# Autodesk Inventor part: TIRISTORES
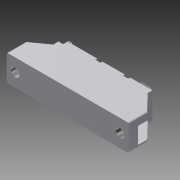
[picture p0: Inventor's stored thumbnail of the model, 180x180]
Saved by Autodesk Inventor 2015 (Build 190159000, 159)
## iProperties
Created: 2016-04
Part Number: TIRISTORES
Material: Genérico
Document SubType Name: Modeling
Designer: Diego
Density: 1 g/cm^3
Appearance: Blanco
Author: Diego
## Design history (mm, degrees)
sketch "Boceto1"
  geometry: L1 (0, 0)-(93, 0); L2 (93, 0)-(93, -20); L3 (93, -20)-(0, -20); L4 (0, -20)-(0, 0)
  constraints: 8 end point, 2 parallel, 1 horizontal, 1 perpendicular
  dimensions: "d0" = 93 distance of L2.end L3.end; "d1" = 20 distance of L1.end L2.end
extrude "Extrusión1" new body sketch "Boceto1" distance "d2" = 7; taper "d3" = 0 deg
sketch "Boceto2"
  geometry: L1 (-93, 0)-(0, 0) reference; 2 further points
hole "Agujero1" sketch "Boceto2" at (-86.5, 10), (-6.5, 10) diameter "d7" = 6.4; stored, may be unused: countersink angle "d11" = 90 deg, drill point angle "d13" = 118 deg; dims "d8" = 12, "d9" = 4, "d10" = 2, "d12" = 17.1
sketch "Boceto3"
  geometry: L1 (0, 0)-(-93, 0); L2 (-93, 0)-(-93, 2); L3 (-93, 2)-(0, 2); L4 (0, 2)-(0, 0)
  constraints: 8 end point, 2 parallel, 1 horizontal, 1 perpendicular
  dimensions: "d14" = 93 distance of L2.end L3.end; "d15" = 2 distance of L1.end L2.end
extrude "Extrusión2" join sketch "Boceto3" distance "d16" = 7; taper "d17" = 0 deg
sketch "Boceto4"
  geometry: L1 (0, 20)-(-93, 20); L2 (-93, 20)-(-93, 18); L3 (-93, 18)-(0, 18); L4 (0, 18)-(0, 20); 1 further point
  constraints: 8 end point, 2 parallel, 1 horizontal, 1 perpendicular
  dimensions: "d18" = 2 distance of L2.end L1.end
extrude "Extrusión3" join sketch "Boceto4" distance "d19" = 7; taper "d20" = 0 deg
sketch "Boceto5"
  geometry: L1 (-93, 20)-(0, 20) reference; L2 (0, 0)-(-93, 0) reference; L3 (-46.5, 20)-(-80.5, 20); L4 (-80.5, 20)-(-80.5, 0); L5 (-80.5, 0)-(-12.5, 0); L6 (-12.5, 0)-(-12.5, 20); L7 (-12.5, 20)-(-46.5, 20)
  constraints: 10 end point, 4 point on line, 1 collinear, 1 midpoint, 1 perpendicular
  dimensions: "d23" = 20 distance of L5.end L6.end
extrude "Extrusión4" join sketch "Boceto5" distance "d24" = 17; taper "d25" = 0 deg
sketch "Boceto6"
  geometry: L1 (0, 0)-(16, 0); L2 (16, 0)-(16, -7); L3 (16, -7)-(0, -7); L4 (0, -7)-(0, 0); 1 further point
  constraints: 8 end point, 2 parallel, 1 horizontal, 1 perpendicular
extrude "Extrusión5" join sketch "Boceto6" distance "d26" = 68; taper "d27" = 0 deg
sketch "Boceto7"
  geometry: L1 (12.5, 31)-(12.5, 27); L2 (12.5, 14)-(12.5, 31) reference; L3 (12.5, 27)-(0, 14); L4 (0, 14)-(12.5, 14); L5 (12.5, 14)-(0, 14) reference; L6 (12.5, 14)-(12.5, 27); 1 further point
  constraints: 8 end point, 1 collinear, 1 perpendicular, 1 point on line
  dimensions: "d28" = 4 distance of L1.start L1.end
extrude "Extrusión6" join sketch "Boceto7" distance "d29" = 2; taper "d30" = 0 deg
sketch "Boceto8"
  geometry: L1 (80.5, 31)-(80.5, 23); L2 (80.5, 14)-(80.5, 31) reference; L3 (80.5, 23)-(93, 14); L4 (93, 14)-(80.5, 14); L5 (80.5, 14)-(80.5, 23); 1 further point
  constraints: 8 end point, 1 collinear, 1 perpendicular, 1 point on line
  dimensions: "d31" = 8 distance of L1.start L1.end
extrude "Extrusión7" join sketch "Boceto8" distance "d32" = 2; taper "d33" = 0 deg
sketch "Boceto9"
  geometry: L1 (12.5, 23)-(0, 14); L2 (12.5, 23)-(0, 14) reference; L3 (0, 14)-(12.5, 14); L4 (12.5, 14)-(0, 14) reference; L5 (12.5, 14)-(12.5, 23); L6 (80.5, 27)-(93, 14); L7 (80.5, 27)-(93, 14) reference; L8 (93, 14)-(80.5, 14); L9 (93, 14)-(80.5, 14) reference; L10 (80.5, 14)-(80.5, 27); 1 further point
  constraints: 12 end point, 4 collinear, 2 perpendicular
extrude "Extrusión8" join sketch "Boceto9" distance "d34" = 2; taper "d35" = 0 deg
sketch "Boceto10"
  geometry: L1 (-80.5, 20)-(-74.5, 20); L2 (-93, 20)-(0, 20) reference; L3 (-74.5, 20)-(-74.5, 11); L4 (-74.5, 11)-(-80.5, 11); L5 (-80.5, 11)-(-80.5, 20); L6 (-74.5, 11)-(-74.5, 0); L7 (-74.5, 0)-(-80.5, 0); L8 (-80.5, 0)-(-12.5, 0) reference; L9 (-80.5, 0)-(-80.5, 9); L10 (-80.5, 20)-(-80.5, 0) reference; L11 (-80.5, 9)-(-74.5, 9); 1 further point
  constraints: 16 end point, 3 point on line, 2 perpendicular, 2 vertical, 1 collinear, 1 horizontal
  dimensions: "d36" = 6 distance of L1.start L1.end; "d37" = 9 distance of L1.end L3.end; "d38" = 9 distance of L7.end L9.end
extrude "Extrusión9" cut sketch "Boceto10" distance "d39" = 4; taper "d40" = 0 deg
sketch "Boceto11"
  geometry: L1 (-80, 11.5)-(-80, 19.5); L2 (-80, 19.5)-(-74.5, 19.5); L3 (-80, 9)-(-80, 0.5); L4 (-80, 0.5)-(-74.5, 0.5); L5 (-74.5, 11)-(-80, 11); L6 (-80, 11)-(-80, 19.5); L7 (-80, 19.5)-(-74.5, 19.5); L8 (-74.5, 19.5)-(-74.5, 11); L9 (-74.5, 9)-(-80, 9); L10 (-80, 9)-(-80, 0.5); L11 (-80, 0.5)-(-74.5, 0.5); L12 (-74.5, 0.5)-(-74.5, 9); 5 further points
  constraints: 24 end point, 4 parallel, 3 perpendicular, 2 horizontal
extrude "Extrusión10" cut sketch "Boceto11" distance "d43" = 4; taper "d44" = 0 deg
chamfer "Chaflán1" distance "d45" = 1; stored, may be unused: second distance "d46" = 2, angle "d47" = 45 deg
chamfer "Chaflán2" distance "d48" = 0.5; stored, may be unused: second distance "d49" = 2, angle "d50" = 45 deg
chamfer "Chaflán3" distance "d51" = 0.5; stored, may be unused: second distance "d52" = 2, angle "d53" = 45 deg
chamfer "Chaflán4" distance "d54" = 0.5; stored, may be unused: second distance "d55" = 2, angle "d56" = 45 deg
fillet "Empalme1" dims "d57" = 1
fillet "Empalme2" dims "d58" = 1
fillet "Empalme3" dims "d59" = 1
fillet "Empalme4" dims "d60" = 1
sketch "Boceto12"
  geometry: L1 (-74.5, 0)-(-12.5, 0) reference; L2 (-12.5, 20)-(-29.5, 20); L3 (-29.5, 20)-(-29.5, 0); L4 (-29.5, 0)-(-12.5, 0); L5 (-12.5, 0)-(-12.5, 20); L6 (-29.5, 20)-(-33.5, 20); L7 (-33.5, 20)-(-33.5, 0); L8 (-33.5, 0)-(-29.5, 0); L9 (-29.5, 0)-(-29.5, 20); L10 (-33.5, 20)-(-50.5, 20); L11 (-50.5, 20)-(-50.5, 0); L12 (-50.5, 0)-(-33.5, 0); L13 (-33.5, 0)-(-33.5, 20); L14 (-50.5, 20)-(-54.5, 20); L15 (-54.5, 20)-(-54.5, 0); L16 (-54.5, 0)-(-50.5, 0); L17 (-50.5, 0)-(-50.5, 20); 1 further point
  constraints: 32 end point, 8 parallel, 4 horizontal, 4 perpendicular, 4 point on line
extrude "Extrusión11" cut sketch "Boceto12" distance "d65" = 2; taper "d66" = 0 deg
sketch "Boceto13"
  geometry: L1 (-13, 0.5)-(-29.5, 0.5) reference; L2 (-33.5, 0.5)-(-50.5, 0.5) reference; 4 further points
hole "Agujero2" sketch "Boceto13" at (-62, 10), (-21.25, 10), (-42, 10) diameter "d68" = 6; stored, may be unused: countersink angle "d72" = 90 deg, drill point angle "d74" = 118 deg; dims "d69" = 12, "d70" = 4, "d71" = 2, "d73" = 5
node "Plano de trabajo1"
sketch "Boceto14"
  geometry: L1 (0, 0)-(2.5, 0); L2 (0, 0)-(19, 0) reference; L3 (2.5, 0)-(2.5, 3); L4 (2.5, 3)-(17.5, 3); L5 (17.5, 3)-(17.5, 1); L6 (17.5, 1)-(4.5, 1); L7 (4.5, 1)-(4.5, 0); L8 (4.5, 0)-(2.5, 0); 1 further point
  constraints: 14 end point, 4 perpendicular, 2 point on line, 1 collinear
  dimensions: "d76" = 2.5 distance of L1.start L1.end; "d77" = 3 distance of L1.end L3.end; "d78" = 15 distance of L3.end L4.end; "d79" = 2 distance of L4.end L5.end; "d80" = 13 distance of L5.end L6.end; "d81" = 1 distance of L6.end L7.end; "d82" = 2 distance of L7.end L1.end (derived)
extrude "Extrusión12" join sketch "Boceto14" stored distance "d83" = 10; taper "d84" = 0 deg
fillet "Empalme5" dims "d85" = 2
chamfer "Chaflán5" distance "d86" = 2; stored, may be unused: second distance "d87" = 2, angle "d88" = 45 deg
chamfer "Chaflán6" distance "d89" = 2; stored, may be unused: second distance "d90" = 2, angle "d91" = 45 deg
sketch "Boceto15"
  geometry: C1 r 3 at (4.75, -5) reference; 2 further points
  constraints: 1 coincident
hole "Agujero3" sketch "Boceto15" at (4.75, -5) diameter "d92" = 6.2; stored, may be unused: countersink angle "d96" = 90 deg, drill point angle "d98" = 118 deg; dims "d93" = 12, "d94" = 4, "d95" = 2, "d97" = 2
node "Plano de trabajo2"
sketch "Boceto16"
  geometry: L1 (15.5, 3)-(15.5, 1) reference; L2 (15.5, 3)-(4.5, 3) reference; L3 (2.5, 1)-(2.5, 0) reference; L4 (4.5, 0)-(2.5, 0) reference; L5 (4.5, 0)-(4.5, 1) reference; L6 (4.5, 1)-(15.5, 1) reference; A1 r 2 centre (4.5, 1) between (4.5, 3) and (2.5, 1) reference; 1 further point
extrude "Extrusión13" join sketch "Boceto16" stored distance "d100" = 10; taper "d101" = 0 deg
node "Plano de trabajo3"
sketch "Boceto17"
  geometry: L1 (3.5, 1)-(3.5, 3) reference; L2 (3.5, 3)-(14.5, 3) reference; L3 (16.5, 1)-(16.5, 0) reference; L4 (14.5, 0)-(16.5, 0) reference; L5 (14.5, 0)-(14.5, 1) reference; L6 (14.5, 1)-(3.5, 1) reference; A1 r 2 centre (14.5, 1) between (16.5, 1) and (14.5, 3) reference; 1 further point
extrude "Extrusión14" join sketch "Boceto17" stored distance "d103" = 10; taper "d104" = 0 deg
sketch "Boceto18"
  geometry: C1 r 3 at (26, 6) reference; C2 r 3 at (6, 6) reference; 3 further points
  constraints: 2 coincident
hole "Agujero4" sketch "Boceto18" at (6, 6), (26, 6) diameter "d105" = 6.2; stored, may be unused: countersink angle "d109" = 90 deg, drill point angle "d111" = 118 deg; dims "d106" = 12, "d107" = 4, "d108" = 2, "d110" = 2
chamfer "Chaflán7" distance "d112" = 2; stored, may be unused: second distance "d113" = 2, angle "d114" = 45 deg
chamfer "Chaflán8" distance "d115" = 2; stored, may be unused: second distance "d116" = 2, angle "d117" = 45 deg
chamfer "Chaflán9" distance "d118" = 2; stored, may be unused: second distance "d119" = 2, angle "d120" = 45 deg
chamfer "Chaflán10" distance "d121" = 2; stored, may be unused: second distance "d122" = 2, angle "d123" = 45 deg
sketch "Boceto19"
  geometry: L1 (-77.25, 17.25)-(-78.75, 17.25); L2 (-78.75, 17.25)-(-78.75, 18.25); L3 (-78.75, 17.25)-(-75.75, 17.25); L4 (-75.75, 17.25)-(-75.75, 18.25); L5 (-75.75, 18.25)-(-78.75, 18.25); L6 (-78.75, 18.25)-(-78.75, 17.25); L7 (-78.75, 13.25)-(-75.75, 13.25); L8 (-75.75, 13.25)-(-75.75, 12.25); L9 (-75.75, 12.25)-(-78.75, 12.25); L10 (-78.75, 13.25)-(-78.75, 12.25); L11 (-73.409, 10)-(-79.5, 10); L12 (-75.75, 7.75)-(-78.75, 7.75); L13 (-78.75, 6.75)-(-75.75, 6.75); L14 (-78.75, 6.75)-(-78.75, 7.75); L15 (-77.25, 2.75)-(-78.75, 2.75); L16 (-78.75, 2.75)-(-75.75, 2.75); L17 (-78.75, 2.75)-(-78.75, 1.75); L18 (-78.75, 1.75)-(-78.75, 2.75); L19 (-75.75, 1.75)-(-78.75, 1.75); L20 (-75.75, 2.75)-(-75.75, 1.75); L21 (-75.75, 6.75)-(-75.75, 7.75); L22 (-75.75, 13.25)-(-78.75, 13.25); L23 (-78.75, 13.25)-(-78.75, 12.25); L24 (-78.75, 12.25)-(-75.75, 12.25); L25 (-75.75, 12.25)-(-75.75, 13.25); L26 (-75.75, 7.75)-(-78.75, 7.75); L27 (-78.75, 7.75)-(-78.75, 6.75); L28 (-78.75, 6.75)-(-75.75, 6.75); L29 (-75.75, 6.75)-(-75.75, 7.75); L30 (-75.75, 2.75)-(-78.75, 2.75); L31 (-78.75, 2.75)-(-78.75, 1.75); L32 (-78.75, 1.75)-(-75.75, 1.75); L33 (-75.75, 1.75)-(-75.75, 2.75); L34 (-75.75, 18.25)-(-78.75, 18.25); L35 (-78.75, 18.25)-(-78.75, 17.25); L36 (-78.75, 17.25)-(-75.75, 17.25); L37 (-75.75, 17.25)-(-75.75, 18.25); 2 further points
  constraints: 74 end point, 10 parallel, 6 horizontal, 6 perpendicular
extrude "Extrusión15" join sketch "Boceto19" distance "d130" = 10; taper "d131" = 0 deg
chamfer "Chaflán11" distance "d132" = 0.75; stored, may be unused: second distance "d133" = 2, angle "d134" = 45 deg
chamfer "Chaflán12" distance "d135" = 0.75; stored, may be unused: second distance "d136" = 2, angle "d137" = 45 deg
chamfer "Chaflán13" distance "d138" = 0.75; stored, may be unused: second distance "d139" = 2, angle "d140" = 45 deg
sketch "Boceto20"
  geometry: L1 (0.75, 10)-(2.25, 10) reference; L2 (1.5, 10)-(1.5, 6.251); C1 r 0.5 at (1.5, 9); 1 further point
  constraints: 2 end point, 1 centre point, 1 midpoint, 1 point on line, 1 vertical
hole "Agujero5" sketch "Boceto20" at (1.5, 9) diameter "d141" = 1; stored, may be unused: countersink angle "d145" = 90 deg, drill point angle "d147" = 118 deg; dims "d142" = 6, "d143" = 4, "d144" = 2, "d146" = 8
sketch "Boceto21"
  geometry: C1 r 3.2 at (-6.5, 10) reference; C2 r 3.2 at (-6.5, 10); C3 r 4.61 at (-6.5, 10); C4 r 3.2 at (-86.5, 10) reference; C5 r 3.2 at (-86.5, 10); C6 r 4.5 at (-86.5, 10); 1 further point
  constraints: 4 centre point, 4 coincident
extrude "Extrusión16" join sketch "Boceto21" distance "d148" = 1; taper "d149" = 0 deg
node "Sólido1"
node "Contorno proyectado1"
node "Contorno proyectado2"
other parameters: "d75" = -8.5, "d99" = -8.5, "d102" = -8.5
